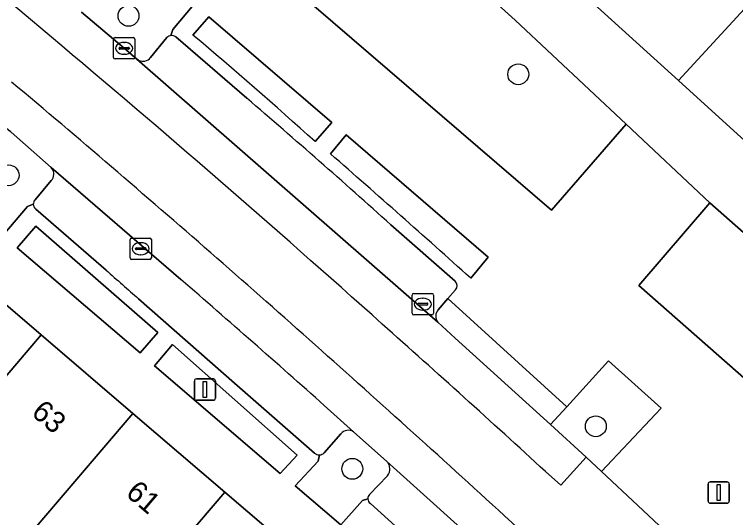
# Model space of a CAD drawing. Extents: x 159716 to 160783, y 383290 to 384031.
# Drawn here: x 160383.63 to 160417.43, y 383661.82 to 383685.43 of the extents above; entities that cross this region are included whole.
import ezdxf

# ---------------------------------------------------------------- set-up
doc = ezdxf.new("R2010")
doc.units = 0
for name, color, linetype in [('IMGEO_Boom', 7, 'Continuous'), ('IMGEO_Groenvoorziening', 7, 'Continuous'), ('IMGEO_Kolk', 7, 'Continuous'), ('IMGEO_Lichtmast', 7, 'Continuous'), ('IMGEO_Pand', 7, 'Continuous'), ('IMGEO_Pand_nummerreeks', 7, 'Continuous'), ('IMGEO_Parkeervlak_open', 7, 'Continuous'), ('IMGEO_Rijbaan_lokaal_gesloten', 7, 'Continuous'), ('IMGEO_Rijbaan_lokaal_open', 7, 'Continuous'), ('IMGEO_Voetpad_open', 7, 'Continuous')]:
    doc.layers.add(name, color=color, linetype=linetype)

msp = doc.modelspace()

# ---------------------------------------------------------------- linework, layer by layer
at = {"layer": 'IMGEO_Boom'}
for centre in [(160388.977, 383685.362), (160407.24, 383682.62), (160383.356, 383677.882), (160410.875, 383666.105), (160399.463, 383664.11)]:
    msp.add_circle(centre, 0.489, dxfattribs=at)
at = {"layer": 'IMGEO_Groenvoorziening'}
for points in [[(160417.14, 383697.859), (160415.253, 383699.577), (160406.662, 383689.674), (160414.756, 383682.321), (160419.662, 383687.67), (160413.231, 383693.288)], [(160403.549, 383688.378), (160392.112, 383698.303), (160388.301, 383693.898), (160408.805, 383676.246), (160412.294, 383680.279), (160407.103, 383685.162)], [(160416.224, 383676.581), (160412.886, 383672.715), (160418.849, 383667.474), (160421.375, 383664.839), (160424.395, 383666.693), (160426.221, 383667.766)], [(160390.343, 383670.505), (160384.626, 383675.494), (160383.759, 383674.476), (160389.525, 383669.55)], [(160396.877, 383664.744), (160391.042, 383669.935), (160390.187, 383668.948), (160396.081, 383663.884)], [(160413.67, 383666.666), (160413.936, 383666.961), (160411.471, 383669.176), (160409.515, 383667.025), (160408.752, 383666.186), (160410.425, 383664.652), (160411.138, 383663.99)]]:
    msp.add_lwpolyline(points, close=True, dxfattribs=at)
for points in [[(160390.966, 383684.436), (160391.049, 383684.717), (160392.042, 383685.9)], [(160386.776, 383685.54), (160388.773, 383683.839), (160389.361, 383683.332), (160389.44, 383683.28)], [(160398.512, 383680.358), (160392.739, 383685.319), (160391.995, 383684.461)], [(160390.009, 383683.409), (160390.773, 383684.349)], [(160397.724, 383679.46), (160398.512, 383680.358)], [(160385.38, 383678.203), (160385.346, 383678.241), (160383.484, 383679.897), (160383.444, 383679.932), (160383.401, 383679.962)], [(160405.011, 383673.06), (160405.835, 383674.044), (160399.18, 383679.774), (160398.444, 383678.888)], [(160381.828, 383678.812), (160381.771, 383678.531), (160380.62, 383677.227), (160383.087, 383675.06), (160384.25, 383676.409), (160384.513, 383676.525)], [(160384.594, 383676.722), (160385.358, 383677.63)], [(160398.931, 383665.755), (160398.144, 383664.855)], [(160401.083, 383664.46), (160399.519, 383665.849)], [(160397.922, 383664.764), (160397.868, 383664.475), (160396.793, 383663.317), (160398.92, 383661.487), (160399.944, 383662.621), (160400.193, 383662.707)], [(160400.264, 383662.9), (160401.116, 383663.785)]]:
    msp.add_lwpolyline(points, dxfattribs=at)
for centre, radius, start, end in [((160248.762, 383514.595), 222.194, 47.90087, 49.86195), ((160390.993, 383684.119), 0.318, 94.8322, 133.6974), ((160389.648, 383683.684), 0.454, 242.8196, 322.728), ((159890.516, 383099.94), 770.176, 48.085389, 48.738575), ((160385.038, 383677.929), 0.438, 316.9267, 38.6758), ((160384.79, 383676.526), 0.277, 135.0629, 180.2354), ((160399.279, 383665.463), 0.454, 58.1088, 140.0566), ((160397.913, 383665.102), 0.338, 271.5028, 313.0756), ((160400.707, 383664.103), 0.518, 322.1077, 43.4901), ((160400.472, 383662.714), 0.279, 138.211, 181.3943)]:
    msp.add_arc(centre, radius, start, end, dxfattribs=at)
at = {"layer": 'IMGEO_Kolk'}
for p, q in [((160388.272, 383683.413), (160388.272, 383684.265)), ((160388.347, 383684.339), (160389.199, 383684.339)), ((160388.76, 383684.119), (160388.785, 383684.119)), ((160389.273, 383684.265), (160389.273, 383683.413)), ((160388.531, 383683.833), (160388.531, 383683.845)), ((160388.969, 383683.796), (160388.571, 383683.796)), ((160388.574, 383683.882), (160388.972, 383683.882)), ((160389.015, 383683.845), (160389.015, 383683.833)), ((160388.783, 383683.559), (160388.758, 383683.559)), ((160389.199, 383683.339), (160388.347, 383683.339)), ((160389.046, 383674.01), (160389.046, 383674.862)), ((160389.121, 383674.936), (160389.973, 383674.936)), ((160389.534, 383674.716), (160389.559, 383674.716)), ((160390.047, 383674.862), (160390.047, 383674.01)), ((160389.305, 383674.43), (160389.305, 383674.442)), ((160389.743, 383674.393), (160389.345, 383674.393)), ((160389.348, 383674.479), (160389.746, 383674.479)), ((160389.789, 383674.442), (160389.789, 383674.43)), ((160389.557, 383674.156), (160389.532, 383674.156)), ((160389.973, 383673.936), (160389.121, 383673.936)), ((160402.343, 383672.334), (160403.195, 383672.334)), ((160402.268, 383671.408), (160402.268, 383672.26)), ((160402.756, 383672.114), (160402.781, 383672.114)), ((160403.269, 383672.26), (160403.269, 383671.408)), ((160402.527, 383671.828), (160402.527, 383671.84)), ((160402.965, 383671.791), (160402.567, 383671.791)), ((160402.57, 383671.877), (160402.968, 383671.877)), ((160403.011, 383671.84), (160403.011, 383671.828)), ((160403.195, 383671.334), (160402.343, 383671.334)), ((160402.779, 383671.554), (160402.754, 383671.554))]:
    msp.add_line(p, q, dxfattribs=at)
for points in [[(160388.272, 383683.413), (160388.272, 383684.265)], [(160388.347, 383684.339), (160389.199, 383684.339)], [(160389.273, 383684.265), (160389.273, 383683.413)], [(160389.199, 383683.339), (160388.347, 383683.339)], [(160389.046, 383674.01), (160389.046, 383674.862)], [(160389.121, 383674.936), (160389.973, 383674.936)], [(160390.047, 383674.862), (160390.047, 383674.01)], [(160389.973, 383673.936), (160389.121, 383673.936)], [(160402.343, 383672.334), (160403.195, 383672.334)], [(160402.268, 383671.408), (160402.268, 383672.26)], [(160403.269, 383672.26), (160403.269, 383671.408)], [(160403.195, 383671.334), (160402.343, 383671.334)]]:
    msp.add_lwpolyline(points, dxfattribs=at)
for centre, radius, start, end in [((160388.349, 383684.263), 0.0765, 91.552, 178.448), ((160388.349, 383684.263), 0.0765, 91.552, 178.448), ((160389.197, 383684.263), 0.0765, 1.552, 88.448), ((160389.197, 383684.263), 0.0765, 1.552, 88.448), ((160388.571, 383683.842), 0.0403, 85.8775, 175.7526), ((160388.568, 383683.832), 0.0366, 178.938, 274.7102), ((160388.972, 383683.839), 0.043, 264.8664, 352.4533), ((160388.976, 383683.844), 0.0386, 1.7309, 96.639), ((160388.349, 383683.415), 0.0765, 181.552, 268.448), ((160388.349, 383683.415), 0.0765, 181.552, 268.448), ((160389.197, 383683.415), 0.0765, 271.552, 358.448), ((160389.197, 383683.415), 0.0765, 271.552, 358.448), ((160389.123, 383674.86), 0.0765, 91.552, 178.448), ((160389.123, 383674.86), 0.0765, 91.552, 178.448), ((160389.971, 383674.86), 0.0765, 1.552, 88.448), ((160389.971, 383674.86), 0.0765, 1.552, 88.448), ((160389.345, 383674.439), 0.0403, 85.8775, 175.7526), ((160389.342, 383674.429), 0.0366, 178.938, 274.7102), ((160389.746, 383674.436), 0.043, 264.8664, 352.4533), ((160389.75, 383674.441), 0.0386, 1.7309, 96.639), ((160389.123, 383674.012), 0.0765, 181.552, 268.448), ((160389.123, 383674.012), 0.0765, 181.552, 268.448), ((160389.971, 383674.012), 0.0765, 271.552, 358.448), ((160389.971, 383674.012), 0.0765, 271.552, 358.448), ((160402.345, 383672.258), 0.0765, 91.552, 178.448), ((160402.345, 383672.258), 0.0765, 91.552, 178.448), ((160403.193, 383672.258), 0.0765, 1.552, 88.448), ((160403.193, 383672.258), 0.0765, 1.552, 88.448), ((160402.567, 383671.837), 0.0403, 85.8775, 175.7526), ((160402.564, 383671.827), 0.0366, 178.938, 274.7102), ((160402.968, 383671.834), 0.043, 264.8664, 352.4533), ((160402.972, 383671.839), 0.0386, 1.7309, 96.639), ((160402.345, 383671.41), 0.0765, 181.552, 268.448), ((160402.345, 383671.41), 0.0765, 181.552, 268.448), ((160403.193, 383671.41), 0.0765, 271.552, 358.448), ((160403.193, 383671.41), 0.0765, 271.552, 358.448)]:
    msp.add_arc(centre, radius, start, end, dxfattribs=at)
for centre, major_axis, ratio, start_param, end_param in [((160388.759, 383683.839), (-0.387, 0.002), 0.722429, 4.712389, 7.853982), ((160388.784, 383683.839), (-0.39, 0.002), 0.717154, 1.570796, 4.712389), ((160389.533, 383674.436), (-0.387, 0.002), 0.722429, 4.712389, 7.853982), ((160389.558, 383674.436), (-0.39, 0.002), 0.717154, 1.570796, 4.712389), ((160402.755, 383671.834), (-0.387, 0.002), 0.722429, 4.712389, 7.853982), ((160402.78, 383671.834), (-0.39, 0.002), 0.717154, 1.570796, 4.712389)]:
    msp.add_ellipse(centre, major_axis=major_axis, ratio=ratio, start_param=start_param, end_param=end_param, dxfattribs=at)
at = {"layer": 'IMGEO_Lichtmast'}
for p, q in [((160392.062, 383667.424), (160392.062, 383668.224)), ((160392.062, 383668.224), (160392.062, 383667.424)), ((160392.162, 383668.324), (160392.952, 383668.324)), ((160392.952, 383668.324), (160392.162, 383668.324)), ((160393.052, 383668.224), (160393.052, 383667.424)), ((160393.052, 383667.424), (160393.052, 383668.224)), ((160392.952, 383667.324), (160392.162, 383667.324)), ((160392.162, 383667.324), (160392.952, 383667.324)), ((160416.238, 383663.494), (160417.028, 383663.494)), ((160417.028, 383663.494), (160416.238, 383663.494)), ((160416.138, 383662.594), (160416.138, 383663.394)), ((160416.138, 383663.394), (160416.138, 383662.594)), ((160417.128, 383663.394), (160417.128, 383662.594)), ((160417.128, 383662.594), (160417.128, 383663.394)), ((160417.028, 383662.494), (160416.238, 383662.494)), ((160416.238, 383662.494), (160417.028, 383662.494))]:
    msp.add_line(p, q, dxfattribs=at)
for points in [[(160392.482, 383668.199), (160392.632, 383668.199), (160392.632, 383667.449), (160392.482, 383667.449), (160392.482, 383668.199)], [(160416.558, 383663.369), (160416.708, 383663.369), (160416.708, 383662.619), (160416.558, 383662.619), (160416.558, 383663.369)]]:
    msp.add_lwpolyline(points, dxfattribs=at)
for centre, start, end in [((160392.162, 383668.224), 90, 180), ((160392.162, 383668.224), 90, 180), ((160392.952, 383668.224), 0, 90), ((160392.952, 383668.224), 360, 90), ((160392.162, 383667.424), 180, 270), ((160392.162, 383667.424), 180, 270), ((160392.952, 383667.424), 270, 0), ((160392.952, 383667.424), 270, 0), ((160416.238, 383663.394), 90, 180), ((160416.238, 383663.394), 90, 180), ((160417.028, 383663.394), 0, 90), ((160417.028, 383663.394), 360, 90), ((160416.238, 383662.594), 180, 270), ((160416.238, 383662.594), 180, 270), ((160417.028, 383662.594), 270, 0), ((160417.028, 383662.594), 270, 0)]:
    msp.add_arc(centre, 0.1, start, end, dxfattribs=at)
at = {"layer": 'IMGEO_Pand'}
for points in [[(160384.875, 383670.399), (160380.565, 383674.091), (160371.31, 383663.249), (160373.49, 383661.388), (160377.861, 383666.541), (160380.026, 383664.694)], [(160389.186, 383666.706), (160384.875, 383670.399), (160380.026, 383664.694), (160379.753, 383664.373), (160381.786, 383662.637), (160377.713, 383657.866), (160379.984, 383655.928), (160380.109, 383656.074)], [(160393.496, 383663.015), (160389.186, 383666.706), (160380.109, 383656.074), (160379.984, 383655.928), (160382.234, 383654.007), (160386.263, 383658.727), (160386.585, 383659.104), (160388.65, 383657.338)], [(160397.807, 383659.322), (160393.496, 383663.015), (160388.65, 383657.338), (160390.046, 383656.145), (160385.793, 383651.162), (160387.066, 383650.075), (160388.712, 383648.669)]]:
    msp.add_lwpolyline(points, close=True, dxfattribs=at)
at = {"layer": 'IMGEO_Parkeervlak_open'}
for points in [[(160390.773, 383684.349), (160390.009, 383683.409)], [(160394.521, 383681.496), (160391.188, 383684.375)], [(160389.44, 383683.28), (160389.361, 383683.332), (160403.476, 383670.988)], [(160391.435, 383672.99), (160385.346, 383678.241), (160385.38, 383678.203)], [(160385.358, 383677.63), (160384.594, 383676.722)], [(160384.631, 383676.297), (160387.935, 383673.429)], [(160404.284, 383672.919), (160401.272, 383675.563)], [(160403.487, 383671.576), (160403.94, 383672.094), (160404.297, 383672.502)], [(160389.447, 383672.088), (160393.945, 383668.124), (160397.699, 383664.837)], [(160399.519, 383665.849), (160398.15, 383667.079)], [(160398.144, 383664.855), (160398.931, 383665.755)], [(160406.076, 383659.917), (160406.096, 383659.939), (160401.083, 383664.46)], [(160401.116, 383663.785), (160400.264, 383662.9)], [(160400.309, 383662.487), (160404.307, 383658.862)]]:
    msp.add_lwpolyline(points, dxfattribs=at)
for centre, radius, start, end in [((160390.993, 383684.119), 0.318, 94.8322, 133.6974), ((160390.998, 383684.117), 0.321, 53.6144, 95.6571), ((160389.648, 383683.684), 0.454, 242.8196, 322.728), ((160113.901, 383355.378), 430.233, 48.09147, 49.2884), ((160385.038, 383677.929), 0.438, 316.9267, 38.6758), ((160384.79, 383676.526), 0.277, 135.0629, 180.2354), ((160384.792, 383676.525), 0.279, 179.9545, 234.7726), ((160452.94, 383745.2), 96.833, 227.83211, 229.02795), ((159962.952, 383179.456), 653.586, 48.251445, 49.035692), ((160404.065, 383672.703), 0.307, 319.0363, 44.5349), ((160403.817, 383671.276), 0.446, 137.7135, 220.1431), ((160399.279, 383665.463), 0.454, 58.1088, 140.0566), ((160397.913, 383665.102), 0.338, 271.5028, 313.0756), ((160397.911, 383665.109), 0.345, 231.9995, 271.7483), ((160400.707, 383664.103), 0.518, 322.1077, 43.4901), ((160400.472, 383662.714), 0.279, 138.211, 181.3943), ((160400.47, 383662.712), 0.277, 181.0858, 234.5171)]:
    msp.add_arc(centre, radius, start, end, dxfattribs=at)
at = {"layer": 'IMGEO_Rijbaan_lokaal_gesloten'}
for points in [[(160367.771, 383695.476), (160365.787, 383697.076), (160364.635, 383695.704), (160367.109, 383693.644), (160368.962, 383692.1), (160369.037, 383692.028), (160383.444, 383679.932), (160383.484, 383679.897), (160385.346, 383678.241), (160391.435, 383672.99)], [(160389.361, 383683.332), (160388.773, 383683.839), (160386.776, 383685.54)], [(160408.512, 383663.988), (160409.243, 383663.343), (160410.425, 383664.652), (160408.752, 383666.186), (160404.289, 383670.243), (160403.476, 383670.988), (160389.361, 383683.332)], [(160398.15, 383667.079), (160399.519, 383665.849), (160401.083, 383664.46), (160406.096, 383659.939), (160407.312, 383661.248), (160406.597, 383661.904)]]:
    msp.add_lwpolyline(points, dxfattribs=at)
for centre, radius, start, end in [((158659.777, 381646.196), 2670.538, 49.747647, 50.188073), ((159981.002, 383203.227), 628.491, 48.083345, 49.955777), ((160162.334, 383417.758), 344.779, 49.07735, 50.09837), ((160019.112, 383246.774), 567.802, 48.21724, 49.45909), ((159962.952, 383179.456), 653.586, 48.251445, 49.035692), ((159988.807, 383207.205), 620.325, 47.422346, 48.374311), ((159862.316, 383068.426), 805.269, 47.47592, 48.353539)]:
    msp.add_arc(centre, radius, start, end, dxfattribs=at)
at = {"layer": 'IMGEO_Rijbaan_lokaal_open'}
for points in [[(160414.587, 383660.793), (160413.843, 383661.455), (160412.842, 383662.391), (160411.138, 383663.99), (160410.425, 383664.652), (160409.243, 383663.343), (160408.512, 383663.988)], [(160406.597, 383661.904), (160407.312, 383661.248), (160406.096, 383659.939), (160406.076, 383659.917), (160406.212, 383659.805)]]:
    msp.add_lwpolyline(points, dxfattribs=at)
for centre, radius, start, end in [((158659.777, 381646.196), 2670.538, 49.747647, 50.188073), ((159981.002, 383203.227), 628.491, 48.083345, 49.955777), ((160162.334, 383417.758), 344.779, 49.07735, 50.09837), ((160019.112, 383246.774), 567.802, 48.21724, 49.45909), ((159988.807, 383207.205), 620.325, 47.422346, 48.374311), ((159862.316, 383068.426), 805.269, 47.47592, 48.353539)]:
    msp.add_arc(centre, radius, start, end, dxfattribs=at)
at = {"layer": 'IMGEO_Voetpad_open'}
for points in [[(160394.044, 383700.656), (160395.427, 383702.249), (160393.513, 383703.895), (160392.245, 383702.203), (160378.05, 383714.53), (160373.434, 383714.511), (160390.192, 383699.969), (160388.371, 383697.872), (160386.357, 383695.552), (160388.301, 383693.898), (160392.112, 383698.303), (160403.549, 383688.378), (160407.103, 383685.162), (160412.294, 383680.279), (160416.224, 383676.581), (160426.221, 383667.766), (160428.304, 383670.305), (160421.081, 383676.575), (160418.373, 383679.035), (160414.756, 383682.321), (160406.662, 383689.674), (160405.79, 383690.466)], [(160384.626, 383675.494), (160390.343, 383670.505), (160389.525, 383669.55), (160383.759, 383674.476)], [(160391.042, 383669.935), (160396.877, 383664.744), (160396.081, 383663.884), (160390.187, 383668.948)]]:
    msp.add_lwpolyline(points, close=True, dxfattribs=at)
for points in [[(160355.902, 383694.92), (160355.799, 383694.787), (160361.049, 383690.367), (160363.163, 383688.996), (160367.634, 383685.167), (160371.944, 383681.475), (160376.255, 383677.783), (160380.565, 383674.091), (160384.875, 383670.399), (160389.186, 383666.706), (160393.496, 383663.015), (160397.807, 383659.322), (160402.121, 383655.627), (160402.445, 383655.31), (160404.075, 383653.502), (160406.534, 383651.357)], [(160422.494, 383660.769), (160423.517, 383661.642), (160424.015, 383662.084), (160421.375, 383664.839), (160418.849, 383667.474), (160412.886, 383672.715), (160416.224, 383676.581), (160412.294, 383680.279), (160408.805, 383676.246), (160388.301, 383693.898)], [(160387.607, 383687.297), (160387.881, 383687.406), (160388.897, 383688.625), (160392.042, 383685.9), (160391.049, 383684.717), (160390.966, 383684.436)], [(160419.662, 383687.67), (160414.756, 383682.321), (160418.373, 383679.035)], [(160391.995, 383684.461), (160392.739, 383685.319)], [(160392.739, 383685.319), (160398.512, 383680.358), (160397.724, 383679.46)], [(160391.188, 383684.375), (160394.521, 383681.496)], [(160398.444, 383678.888), (160399.18, 383679.774)], [(160399.18, 383679.774), (160405.835, 383674.044), (160405.011, 383673.06)], [(160384.513, 383676.525), (160384.25, 383676.409), (160383.087, 383675.06), (160380.62, 383677.227), (160381.771, 383678.531), (160381.828, 383678.812)], [(160387.935, 383673.429), (160384.631, 383676.297)], [(160401.272, 383675.563), (160404.284, 383672.919)], [(160404.297, 383672.502), (160403.94, 383672.094), (160409.515, 383667.025), (160411.471, 383669.176), (160413.936, 383666.961), (160413.67, 383666.666), (160411.138, 383663.99), (160412.842, 383662.391), (160413.843, 383661.455), (160414.587, 383660.793)], [(160397.699, 383664.837), (160393.945, 383668.124), (160389.447, 383672.088)], [(160403.476, 383670.988), (160404.289, 383670.243), (160408.752, 383666.186), (160409.515, 383667.025), (160403.94, 383672.094)], [(160403.94, 383672.094), (160403.487, 383671.576)], [(160400.193, 383662.707), (160399.944, 383662.621), (160398.92, 383661.487), (160396.793, 383663.317), (160397.868, 383664.475), (160397.922, 383664.764)], [(160404.307, 383658.862), (160400.309, 383662.487)]]:
    msp.add_lwpolyline(points, dxfattribs=at)
for centre, radius, start, end in [((160248.762, 383514.595), 222.194, 47.90087, 49.86195), ((160390.998, 383684.117), 0.321, 53.6144, 95.6571), ((160113.901, 383355.378), 430.233, 48.09147, 49.2884), ((159890.516, 383099.94), 770.176, 48.085389, 48.738575), ((160384.792, 383676.525), 0.279, 179.9545, 234.7726), ((160452.94, 383745.2), 96.833, 227.83211, 229.02795), ((160404.065, 383672.703), 0.307, 319.0363, 44.5349), ((160403.817, 383671.276), 0.446, 137.7135, 220.1431), ((160397.911, 383665.109), 0.345, 231.9995, 271.7483), ((160400.47, 383662.712), 0.277, 181.0858, 234.5171)]:
    msp.add_arc(centre, radius, start, end, dxfattribs=at)

# ---------------------------------------------------------------- texts
at = {"layer": 'IMGEO_Pand_nummerreeks'}
for s, p in [('63', (160384.369, 383666.665)), ('61', (160388.792, 383662.889))]:
    msp.add_text(s, height=1, rotation=319.5148, dxfattribs=at).set_placement(p)

doc.saveas('drawing.dxf')
